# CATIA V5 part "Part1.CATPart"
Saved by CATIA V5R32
Part number: Part1
Bounding box of the stored display mesh (mm): x -50 to 50, y -25 to 25, z -25 to 25
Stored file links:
  D:\PROJECTS\Project 2022\CATIA V5 6R 2022\Resources\Part Files\c16_catia_v5_6r2022_prt\Spherical Joint-(Fig16-27)\Part1.CATPart
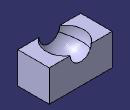
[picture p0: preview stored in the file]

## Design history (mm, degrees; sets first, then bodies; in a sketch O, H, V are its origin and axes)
Body1 (main body)
  Sketch1 on xy-plane, origin (0, 0, 0), H (1, 0, 0), V (0, 1, 0)
    line L1 (50, 25) -> (50, -25)
    line L2 (50, -25) -> (-50, -25)
    line L3 (-50, -25) -> (-50, 25)
    line L4 (-50, 25) -> (50, 25)
    length L4 = 100
    length L1 = 50
    vertical: L1 V, L3 V
    horizontal: L2 H, L4 H
    equidistance: L1 L3 O, L2 L4 O
  Pad1: profile Sketch1, direction (0, 0, 1), length 25, mirrored extent
  Sketch2 on end face of Pad1, origin (0, 0, 25), H (1, 0, 0), V (0, 1, 0)
    line L1 (0, -30) -> (0, 30)
    point P1 (0, -30)
    point P2 (0, 30)
    arc A1 centre (0, 0) radius 30 from (0, -30) to (0, 30) ccw
    point P3 (0, 30)
    radius A1 = 30
    coincidence: P1 V, P3 P2
    vertical: L1 V
  Groove1: profile Sketch2, axis Sketch2.L1, angle 360
  Point1: type OnSurface, Support face of Groove1 from Sketch2.A1, Length 30.441, Direction (-0.8348, -0.4546, 0.3105)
